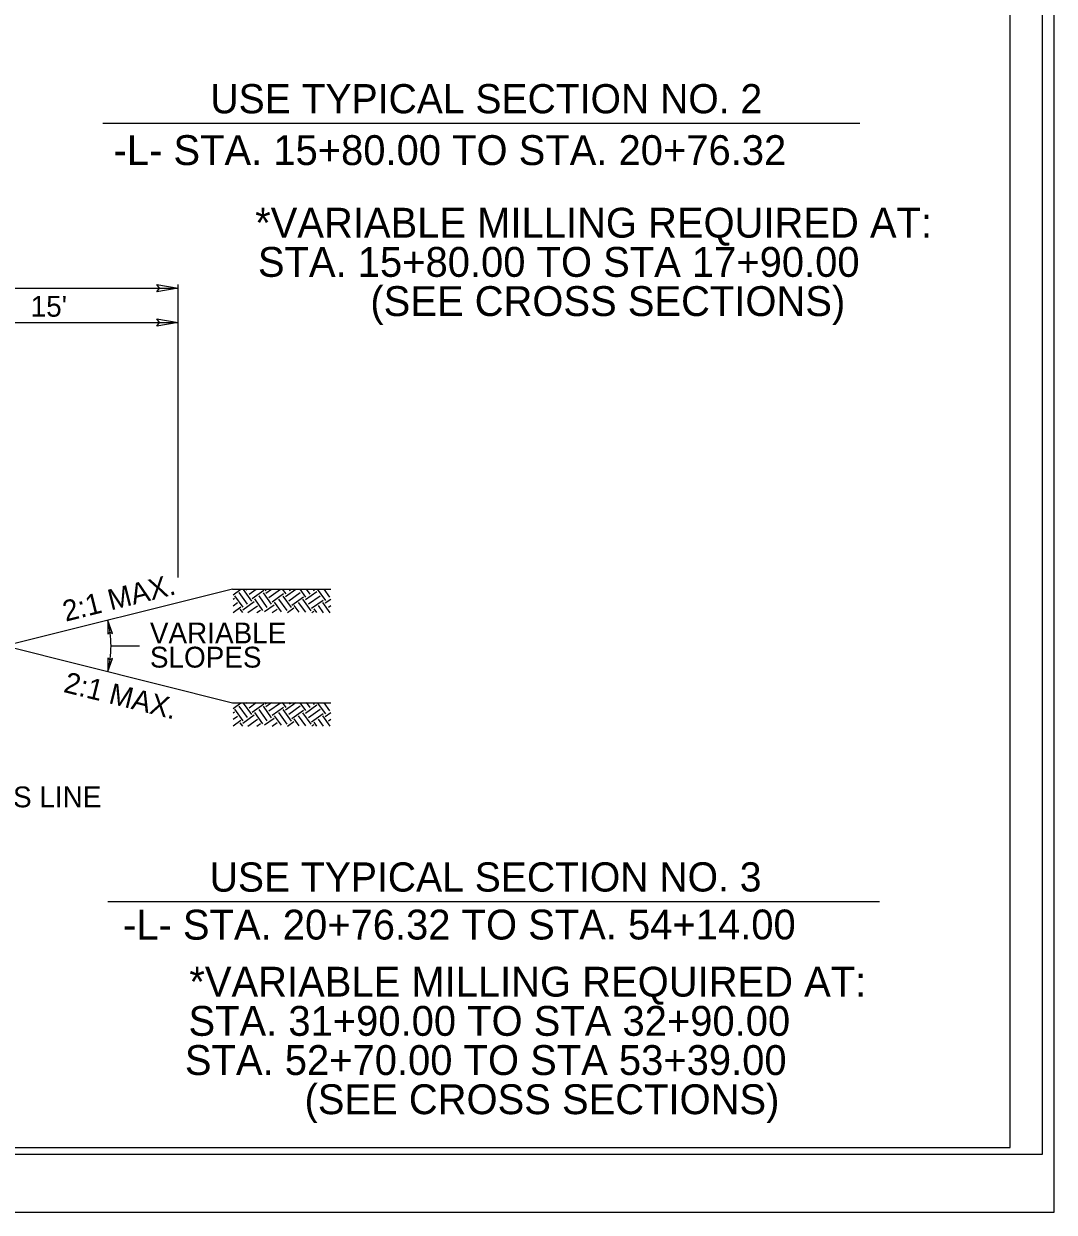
# Model space of a CAD drawing. Extents: x 3025871 to 3026431, y 707165 to 707825.
# Drawn here: x 3026214.9 to 3026274.6, y 707570.3 to 707639.3 of the extents above; entities that cross this region are included whole.
import ezdxf

# ---------------------------------------------------------------- set-up
doc = ezdxf.new("R2010")
doc.units = 0
for name, color, linetype in [('Old_Level_39', 7, 'Continuous'), ('Prop Drainage Structure Junction Box with Slab Lid TB 840 34 CELL', 7, 'Continuous'), ('Sheet Cutting Line CELL', 7, 'Continuous'), ('Typical Terminator CELL', 7, 'Continuous'), ('Typical Text Centerline CELL', 7, 'Continuous'), ('Typical Text Grade Point CELL', 7, 'Continuous')]:
    doc.layers.add(name, color=color, linetype=linetype)

msp = doc.modelspace()

# ---------------------------------------------------------------- linework, layer by layer
at = {"layer": 'Old_Level_39'}
msp.add_lwpolyline([(3026273.948, 707731.968), (3026023.973, 707731.968), (3026023.973, 707573.703), (3026273.948, 707573.703)], close=True, dxfattribs=at)
at = {"layer": 'Prop Drainage Structure Junction Box with Slab Lid TB 840 34 CELL'}
for p, q in [((3026219.465, 707633.51), (3026263.351, 707633.51)), ((3026129.313, 707623.941), (3026223.827, 707623.941)), ((3026223.827, 707607.152), (3026223.827, 707624.152)), ((3026208.827, 707621.941), (3026223.827, 707621.941)), ((3026219.943, 707603.18), (3026221.599, 707603.18)), ((3026219.763, 707588.365), (3026264.497, 707588.365))]:
    msp.add_line(p, q, dxfattribs=at)
msp.add_arc((3026213.827, 707603.18), 6.116, 345.96376, 14.03624, dxfattribs=at)
at = {"layer": 'Sheet Cutting Line CELL'}
msp.add_lwpolyline([(3026272.073, 707731.586), (3026047.073, 707731.586), (3026047.073, 707574.086), (3026272.073, 707574.086)], close=True, dxfattribs=at)
at = {"layer": 'Typical Terminator CELL'}
msp.add_lwpolyline([(3026274.623, 707735.336), (3026022.023, 707735.336), (3026022.023, 707570.336), (3026274.623, 707570.336)], close=True, dxfattribs=at)
at = {"layer": 'Typical Text Centerline CELL'}
for points in [[(3026222.602, 707624.152), (3026223.827, 707623.941), (3026222.595, 707623.723), (3026222.752, 707623.941)], [(3026222.602, 707622.152), (3026223.827, 707621.941), (3026222.595, 707621.723), (3026222.752, 707621.941)], [(3026220.024, 707603.906), (3026219.76, 707604.663), (3026219.752, 707603.856), (3026219.874, 707603.979)], [(3026219.757, 707602.498), (3026219.76, 707601.697), (3026220.03, 707602.457), (3026219.875, 707602.38)]]:
    msp.add_lwpolyline(points, close=True, dxfattribs=at)
at = {"layer": 'Typical Text Grade Point CELL'}
for p, q in [((3026226.993, 707606.471), (3026213.827, 707603.18)), ((3026226.993, 707606.471), (3026232.677, 707606.471)), ((3026226.993, 707606.471), (3026232.677, 707606.471)), ((3026227.014, 707606.142), (3026227.474, 707606.472)), ((3026227.014, 707606.142), (3026227.474, 707606.472)), ((3026228.104, 707605.785), (3026227.624, 707606.453)), ((3026228.104, 707605.785), (3026227.624, 707606.453)), ((3026227.768, 707606.43), (3026227.828, 707606.473)), ((3026227.768, 707606.43), (3026227.828, 707606.473)), ((3026227.948, 707606.179), (3026228.359, 707606.475)), ((3026227.948, 707606.179), (3026228.359, 707606.475)), ((3026228.94, 707606.385), (3026228.875, 707606.476)), ((3026228.94, 707606.385), (3026228.875, 707606.476)), ((3026228.916, 707606.242), (3026229.244, 707606.477)), ((3026228.916, 707606.242), (3026229.244, 707606.477)), ((3026229.097, 707605.991), (3026229.765, 707606.471)), ((3026229.097, 707605.991), (3026229.765, 707606.471)), ((3026230.089, 707606.197), (3026229.886, 707606.479)), ((3026230.089, 707606.197), (3026229.886, 707606.479)), ((3026230.065, 707606.054), (3026230.66, 707606.481)), ((3026230.065, 707606.054), (3026230.66, 707606.481)), ((3026230.339, 707606.377), (3026230.265, 707606.48)), ((3026230.339, 707606.377), (3026230.265, 707606.48)), ((3026231.237, 707606.009), (3026230.905, 707606.471)), ((3026231.237, 707606.009), (3026230.905, 707606.471)), ((3026231.488, 707606.189), (3026231.277, 707606.483)), ((3026231.488, 707606.189), (3026231.277, 707606.483)), ((3026231.739, 707606.369), (3026231.666, 707606.471)), ((3026231.739, 707606.369), (3026231.666, 707606.471)), ((3026232.386, 707605.821), (3026231.919, 707606.471)), ((3026232.386, 707605.821), (3026231.919, 707606.471)), ((3026232.637, 707606.001), (3026232.299, 707606.471)), ((3026232.637, 707606.001), (3026232.299, 707606.471)), ((3026227.014, 707605.888), (3026227.099, 707605.949)), ((3026227.014, 707605.888), (3026227.099, 707605.949)), ((3026227.603, 707605.425), (3026227.123, 707606.093)), ((3026227.603, 707605.425), (3026227.123, 707606.093)), ((3026227.854, 707605.605), (3026227.373, 707606.273)), ((3026227.854, 707605.605), (3026227.373, 707606.273)), ((3026227.58, 707605.281), (3026228.248, 707605.761)), ((3026227.58, 707605.281), (3026228.248, 707605.761)), ((3026228.128, 707605.928), (3026228.796, 707606.409)), ((3026228.128, 707605.928), (3026228.796, 707606.409)), ((3026228.752, 707605.237), (3026228.272, 707605.905)), ((3026228.752, 707605.237), (3026228.272, 707605.905)), ((3026229.003, 707605.417), (3026228.522, 707606.085)), ((3026229.003, 707605.417), (3026228.522, 707606.085)), ((3026229.253, 707605.597), (3026228.773, 707606.265)), ((3026229.253, 707605.597), (3026228.773, 707606.265)), ((3026229.277, 707605.74), (3026229.945, 707606.221)), ((3026229.277, 707605.74), (3026229.945, 707606.221)), ((3026230.151, 707605.229), (3026229.671, 707605.897)), ((3026230.151, 707605.229), (3026229.671, 707605.897)), ((3026230.402, 707605.409), (3026229.922, 707606.077)), ((3026230.402, 707605.409), (3026229.922, 707606.077)), ((3026230.245, 707605.803), (3026230.914, 707606.283)), ((3026230.245, 707605.803), (3026230.914, 707606.283)), ((3026230.425, 707605.552), (3026231.094, 707606.033)), ((3026230.425, 707605.552), (3026231.094, 707606.033)), ((3026231.551, 707605.221), (3026231.07, 707605.889)), ((3026231.551, 707605.221), (3026231.07, 707605.889)), ((3026231.214, 707605.866), (3026231.882, 707606.346)), ((3026231.214, 707605.866), (3026231.882, 707606.346)), ((3026231.394, 707605.615), (3026232.062, 707606.095)), ((3026231.394, 707605.615), (3026232.062, 707606.095)), ((3026231.574, 707605.364), (3026232.243, 707605.845)), ((3026231.574, 707605.364), (3026232.243, 707605.845)), ((3026232.363, 707605.678), (3026232.677, 707605.903)), ((3026232.363, 707605.678), (3026232.677, 707605.903)), ((3026227.014, 707605.508), (3026227.279, 707605.699)), ((3026227.014, 707605.508), (3026227.279, 707605.699)), ((3026227.014, 707605.128), (3026227.46, 707605.448)), ((3026227.014, 707605.128), (3026227.46, 707605.448)), ((3026227.575, 707605.111), (3026227.436, 707605.305)), ((3026227.575, 707605.111), (3026227.436, 707605.305)), ((3026227.872, 707605.111), (3026228.428, 707605.511)), ((3026227.872, 707605.111), (3026228.428, 707605.511)), ((3026228.401, 707605.111), (3026228.608, 707605.26)), ((3026228.401, 707605.111), (3026228.608, 707605.26)), ((3026228.848, 707605.179), (3026229.397, 707605.573)), ((3026228.848, 707605.179), (3026229.397, 707605.573)), ((3026229.282, 707605.111), (3026229.577, 707605.323)), ((3026229.282, 707605.111), (3026229.577, 707605.323)), ((3026229.821, 707605.159), (3026229.42, 707605.717)), ((3026229.821, 707605.159), (3026229.42, 707605.717)), ((3026230.164, 707605.111), (3026230.545, 707605.385)), ((3026230.164, 707605.111), (3026230.545, 707605.385)), ((3026230.849, 707605.139), (3026230.569, 707605.529)), ((3026230.849, 707605.139), (3026230.569, 707605.529)), ((3026231.235, 707605.131), (3026230.82, 707605.709)), ((3026231.235, 707605.131), (3026230.82, 707605.709)), ((3026231.592, 707605.124), (3026231.694, 707605.197)), ((3026231.592, 707605.124), (3026231.694, 707605.197)), ((3026231.878, 707605.118), (3026231.718, 707605.341)), ((3026231.878, 707605.118), (3026231.718, 707605.341)), ((3026232.263, 707605.11), (3026231.968, 707605.521)), ((3026232.263, 707605.11), (3026231.968, 707605.521)), ((3026232.649, 707605.103), (3026232.219, 707605.701)), ((3026232.649, 707605.103), (3026232.219, 707605.701)), ((3026232.543, 707605.427), (3026232.677, 707605.523)), ((3026232.543, 707605.427), (3026232.677, 707605.523)), ((3026213.827, 707603.18), (3026226.993, 707599.889)), ((3026226.993, 707599.889), (3026232.677, 707599.889)), ((3026226.993, 707599.889), (3026232.677, 707599.889)), ((3026227.014, 707599.559), (3026227.474, 707599.89)), ((3026227.014, 707599.559), (3026227.474, 707599.89)), ((3026227.854, 707599.022), (3026227.373, 707599.691)), ((3026227.854, 707599.022), (3026227.373, 707599.691)), ((3026228.104, 707599.202), (3026227.624, 707599.871)), ((3026228.104, 707599.202), (3026227.624, 707599.871)), ((3026227.768, 707599.847), (3026227.828, 707599.891)), ((3026227.768, 707599.847), (3026227.828, 707599.891)), ((3026227.948, 707599.597), (3026228.359, 707599.892)), ((3026227.948, 707599.597), (3026228.359, 707599.892)), ((3026228.128, 707599.346), (3026228.796, 707599.826)), ((3026228.128, 707599.346), (3026228.796, 707599.826)), ((3026229.253, 707599.014), (3026228.773, 707599.683)), ((3026229.253, 707599.014), (3026228.773, 707599.683)), ((3026228.94, 707599.803), (3026228.875, 707599.894)), ((3026228.94, 707599.803), (3026228.875, 707599.894)), ((3026228.916, 707599.659), (3026229.244, 707599.895)), ((3026228.916, 707599.659), (3026229.244, 707599.895)), ((3026229.097, 707599.408), (3026229.765, 707599.889)), ((3026229.097, 707599.408), (3026229.765, 707599.889)), ((3026229.277, 707599.158), (3026229.945, 707599.638)), ((3026229.277, 707599.158), (3026229.945, 707599.638)), ((3026230.089, 707599.615), (3026229.886, 707599.896)), ((3026230.089, 707599.615), (3026229.886, 707599.896)), ((3026230.065, 707599.471), (3026230.66, 707599.899)), ((3026230.065, 707599.471), (3026230.66, 707599.899)), ((3026230.245, 707599.22), (3026230.914, 707599.701)), ((3026230.245, 707599.22), (3026230.914, 707599.701)), ((3026230.339, 707599.795), (3026230.265, 707599.898)), ((3026230.339, 707599.795), (3026230.265, 707599.898)), ((3026231.237, 707599.427), (3026230.905, 707599.889)), ((3026231.237, 707599.427), (3026230.905, 707599.889)), ((3026231.214, 707599.283), (3026231.882, 707599.763)), ((3026231.214, 707599.283), (3026231.882, 707599.763)), ((3026231.488, 707599.607), (3026231.277, 707599.9)), ((3026231.488, 707599.607), (3026231.277, 707599.9)), ((3026231.739, 707599.787), (3026231.666, 707599.889)), ((3026231.739, 707599.787), (3026231.666, 707599.889)), ((3026232.386, 707599.239), (3026231.919, 707599.889)), ((3026232.386, 707599.239), (3026231.919, 707599.889)), ((3026232.637, 707599.419), (3026232.299, 707599.889)), ((3026232.637, 707599.419), (3026232.299, 707599.889)), ((3026227.014, 707599.306), (3026227.099, 707599.367)), ((3026227.014, 707599.306), (3026227.099, 707599.367)), ((3026227.014, 707598.926), (3026227.279, 707599.116)), ((3026227.014, 707598.926), (3026227.279, 707599.116)), ((3026227.014, 707598.546), (3026227.46, 707598.866)), ((3026227.014, 707598.546), (3026227.46, 707598.866)), ((3026227.603, 707598.842), (3026227.123, 707599.51)), ((3026227.603, 707598.842), (3026227.123, 707599.51)), ((3026227.58, 707598.698), (3026228.248, 707599.179)), ((3026227.58, 707598.698), (3026228.248, 707599.179)), ((3026227.872, 707598.528), (3026228.428, 707598.928)), ((3026227.872, 707598.528), (3026228.428, 707598.928)), ((3026228.752, 707598.654), (3026228.272, 707599.322)), ((3026228.752, 707598.654), (3026228.272, 707599.322)), ((3026229.003, 707598.834), (3026228.522, 707599.503)), ((3026229.003, 707598.834), (3026228.522, 707599.503)), ((3026228.848, 707598.596), (3026229.397, 707598.991)), ((3026228.848, 707598.596), (3026229.397, 707598.991)), ((3026229.821, 707598.577), (3026229.42, 707599.134)), ((3026229.821, 707598.577), (3026229.42, 707599.134)), ((3026230.151, 707598.646), (3026229.671, 707599.314)), ((3026230.151, 707598.646), (3026229.671, 707599.314)), ((3026230.402, 707598.826), (3026229.922, 707599.495)), ((3026230.402, 707598.826), (3026229.922, 707599.495)), ((3026230.425, 707598.97), (3026231.094, 707599.45)), ((3026230.425, 707598.97), (3026231.094, 707599.45)), ((3026230.849, 707598.556), (3026230.569, 707598.946)), ((3026230.849, 707598.556), (3026230.569, 707598.946)), ((3026231.235, 707598.548), (3026230.82, 707599.126)), ((3026231.235, 707598.548), (3026230.82, 707599.126)), ((3026231.551, 707598.638), (3026231.07, 707599.307)), ((3026231.551, 707598.638), (3026231.07, 707599.307)), ((3026231.394, 707599.032), (3026232.062, 707599.513)), ((3026231.394, 707599.032), (3026232.062, 707599.513)), ((3026231.574, 707598.782), (3026232.243, 707599.262)), ((3026231.574, 707598.782), (3026232.243, 707599.262)), ((3026232.263, 707598.528), (3026231.968, 707598.938)), ((3026232.263, 707598.528), (3026231.968, 707598.938)), ((3026232.649, 707598.52), (3026232.219, 707599.118)), ((3026232.649, 707598.52), (3026232.219, 707599.118)), ((3026232.363, 707599.095), (3026232.677, 707599.321)), ((3026232.363, 707599.095), (3026232.677, 707599.321)), ((3026232.543, 707598.844), (3026232.677, 707598.941)), ((3026232.543, 707598.844), (3026232.677, 707598.941)), ((3026227.575, 707598.528), (3026227.436, 707598.722)), ((3026227.575, 707598.528), (3026227.436, 707598.722)), ((3026228.401, 707598.528), (3026228.608, 707598.678)), ((3026228.401, 707598.528), (3026228.608, 707598.678)), ((3026229.282, 707598.528), (3026229.577, 707598.74)), ((3026229.282, 707598.528), (3026229.577, 707598.74)), ((3026230.164, 707598.528), (3026230.545, 707598.803)), ((3026230.164, 707598.528), (3026230.545, 707598.803)), ((3026231.592, 707598.541), (3026231.694, 707598.615)), ((3026231.592, 707598.541), (3026231.694, 707598.615)), ((3026231.878, 707598.535), (3026231.718, 707598.758)), ((3026231.878, 707598.535), (3026231.718, 707598.758))]:
    msp.add_line(p, q, dxfattribs=at)

# ---------------------------------------------------------------- texts
at = {"layer": 'Prop Drainage Structure Junction Box with Slab Lid TB 840 34 CELL'}
for s, height, rotation, p in [('USE TYPICAL SECTION NO. 2', 1.69489, 360, (3026225.703, 707634.073)), ('-L- STA. 15+80.00 TO STA. 20+76.32', 1.73151, 360, (3026220.089, 707631.073)), ('*VARIABLE MILLING REQUIRED AT:', 1.73151, 360, (3026228.299, 707626.862)), ('STA. 15+80.00 TO STA 17+90.00', 1.73151, 360, (3026228.458, 707624.589)), ('(SEE CROSS SECTIONS)', 1.73151, 360, (3026234.977, 707622.316)), ('USE TYPICAL SECTION NO. 3', 1.69489, 0.01959, (3026225.663, 707588.928)), ('-L- STA. 20+76.32 TO STA. 54+14.00', 1.73151, 0.01959, (3026220.638, 707586.146)), ('*VARIABLE MILLING REQUIRED AT:', 1.73151, 360, (3026224.482, 707582.841)), ('STA. 31+90.00 TO STA 32+90.00', 1.73151, 360, (3026224.434, 707580.568)), ('STA. 52+70.00 TO STA 53+39.00', 1.73151, 360, (3026224.226, 707578.296)), ('(SEE CROSS SECTIONS)', 1.73151, 360, (3026231.16, 707576.023))]:
    msp.add_text(s, height=height, rotation=rotation, dxfattribs=at).set_placement(p)
for s, height, p in [("15'", 1.2089, (3026215.285, 707622.276)), ('GRADE TO THIS LINE', 1.20892, (3026202.765, 707593.82))]:
    msp.add_text(s, height=height, dxfattribs=at).set_placement(p)
at = {"layer": 'Typical Text Grade Point CELL'}
for rotation, p in [(14.03624, (3026217.314, 707604.582)), (345.96376, (3026217.135, 707600.522))]:
    msp.add_text('2:1 MAX.', height=1.2089, rotation=rotation, dxfattribs=at).set_placement(p)
for s, p in [('VARIABLE', (3026222.197, 707603.328)), ('SLOPES', (3026222.197, 707601.925))]:
    msp.add_text(s, height=1.2089, dxfattribs=at).set_placement(p)

doc.saveas('drawing.dxf')
